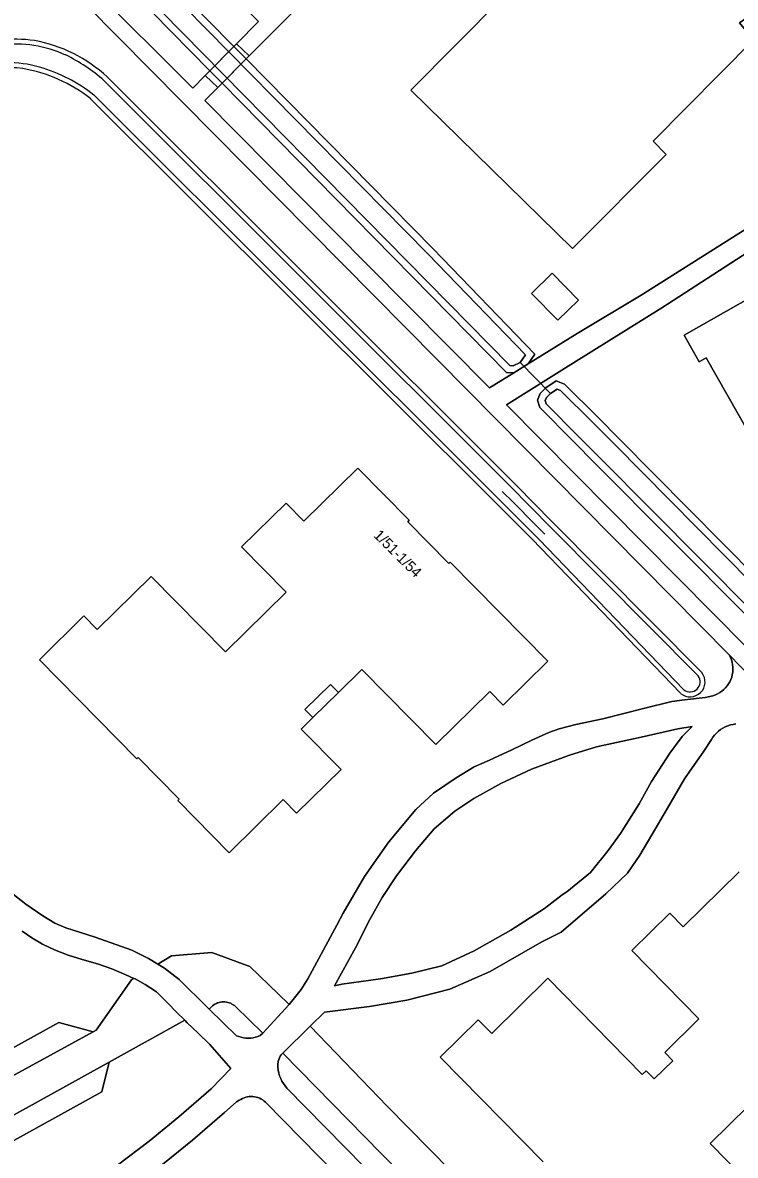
# Model space of a CAD drawing. Extents: x 162788 to 163838, y 385791 to 386523.
# Drawn here: x 162931.3 to 162998.4, y 386105.3 to 386211.9 of the extents above; entities that cross this region are included whole.
import ezdxf

# ---------------------------------------------------------------- set-up
doc = ezdxf.new("R2010")
doc.units = 0
for name, color, linetype in [('IMGEO_Berm_groen', 7, 'Continuous'), ('IMGEO_Dek', 7, 'Continuous'), ('IMGEO_Duiker', 7, 'Continuous'), ('IMGEO_Erf', 7, 'Continuous'), ('IMGEO_Groenvoorziening', 7, 'Continuous'), ('IMGEO_Oever', 7, 'Continuous'), ('IMGEO_Pand', 7, 'Continuous'), ('IMGEO_Pand_nummerreeks', 7, 'Continuous'), ('IMGEO_Pand_overbouw', 7, 'Continuous'), ('IMGEO_Parkeervlak_open', 7, 'Continuous'), ('IMGEO_Voetpad_open', 7, 'Continuous'), ('IMGEO_Waterloop', 7, 'Continuous'), ('IMGEO_Woonerf_gesloten', 7, 'Continuous'), ('IMGEO_Woonerf_open', 7, 'Continuous')]:
    doc.layers.add(name, color=color, linetype=linetype)

msp = doc.modelspace()

# ---------------------------------------------------------------- linework, layer by layer
at = {"layer": 'IMGEO_Berm_groen'}
msp.add_lwpolyline([(162965.08, 386105.45), (162955.83, 386114.88), (162955.67, 386114.72), (162955.58, 386114.62), (162955.43, 386114.28), (162955.37, 386114.1), (162955.36, 386113.83), (162955.36, 386113.56), (162955.39, 386113.29), (162955.45, 386113.02), (162955.52, 386112.76), (162955.62, 386112.51), (162955.74, 386112.26), (162955.87, 386112.02), (162956.03, 386111.8), (162956.21, 386111.59), (162968.96, 386098.61), (162970.91, 386096.63), (162971.01, 386099.41)], close=True, dxfattribs=at)
at = {"layer": 'IMGEO_Dek'}
msp.add_lwpolyline([(162952.65, 386208.77), (162951.46, 386209.9), (162948.52, 386206.92), (162949.69, 386205.79)], close=True, dxfattribs=at)
at = {"layer": 'IMGEO_Duiker'}
for points in [[(162981.02, 386176.99), (162978.18, 386179.89)], [(162980.5, 386163.74), (162979.58, 386164.66), (162977.5, 386166.74), (162976.48, 386167.77)]]:
    msp.add_lwpolyline(points, dxfattribs=at)
at = {"layer": 'IMGEO_Erf'}
for points in [[(162975.18, 386223.84), (162974.7, 386223.35), (162973.45, 386222.08), (162966.27, 386214.77), (162962.88, 386218.16), (162961.69, 386216.94), (162961.22, 386217.38), (162952.65, 386208.77), (162952.36, 386208.48), (162969.98, 386190.59), (162979.54, 386180.69), (162978.92, 386179.77), (162983.54, 386182.64), (162989.55, 386186.25), (163000.56, 386193.16), (163003.46, 386197.1), (163012.04, 386206.87), (163017.41, 386210.52), (163018.58, 386211.64), (163019.24, 386212.57)], [(163019.42, 386221.83), (163017.21, 386224.9), (163006.51, 386217.25), (163004.81, 386216.06), (162998.84, 386211.87), (163000, 386210.45), (163000.14, 386210.28), (162990.68, 386200.74), (162991.91, 386199.49), (162983.1, 386190.62), (162967.86, 386205.52), (162976.44, 386214.19), (162973.67, 386216.9), (162977.86, 386221.23), (162975.18, 386223.84)], [(162929.85, 386130.29), (162931.63, 386128.9), (162933.21, 386127.82), (162934.34, 386127.14), (162935.39, 386126.67), (162938.14, 386125.82), (162941.59, 386124.58), (162943.17, 386123.81), (162944.05, 386123.27), (162945.35, 386124.05), (162949.12, 386124.35), (162952.7, 386123.04), (162956.32, 386119.57), (162956.41, 386119.48), (162956.54, 386119.62), (162957.55, 386120.87), (162958.17, 386121.89), (162960.89, 386126.93), (162961.51, 386128.07), (162963.51, 386131.51), (162965.8, 386134.77), (162968.35, 386137.83), (162970.01, 386139.37), (162972.14, 386140.8), (162973.85, 386141.84), (162975.27, 386142.48), (162977.38, 386143.43), (162979.28, 386144.36), (162980.86, 386145.08), (162981.83, 386145.41), (162982.69, 386145.64), (162983.42, 386145.82), (162985.94, 386146.37), (162989.92, 386147.35), (162992.46, 386147.98), (162993.65, 386148.16), (162995.58, 386148.38), (162996.32, 386148.53), (162996.55, 386148.61), (162996.76, 386148.71), (162996.97, 386148.83), (162997.16, 386148.96), (162997.34, 386149.11), (162997.51, 386149.28), (162997.66, 386149.46), (162997.8, 386149.65), (162997.92, 386149.85), (162998.01, 386150.07), (162998.09, 386150.29), (162998.15, 386150.52), (162998.19, 386150.75), (162998.21, 386150.98), (162998.21, 386151.22), (162998.18, 386151.45), (162998.14, 386151.68), (162998.07, 386151.91), (162997.99, 386152.13), (162997.88, 386152.34), (162970.37, 386180.14), (162937.33, 386213.52)], [(162939.28, 386206.78), (162977.87, 386168.3), (162981.13, 386164.95), (162995.27, 386150.72)], [(162975.88, 386166.68), (162937.72, 386204.73)], [(163001.75, 386191.66), (162991.5, 386185.05), (162983.2, 386179.88), (162976.87, 386175.9), (163002.73, 386149.83)], [(163000.73, 386171.45), (162995.7, 386180.34), (162995.02, 386179.96), (162993.61, 386182.46), (163004.02, 386188.36)], [(162993.27, 386148.76), (162979.3, 386163.28), (162975.88, 386166.68)], [(162998.48, 386145.88), (162998.22, 386145.84), (162997.97, 386145.78), (162997.73, 386145.7), (162997.49, 386145.6), (162997.26, 386145.48), (162997.05, 386145.35), (162996.84, 386145.19), (162996.65, 386145.02), (162996.48, 386144.83), (162996.32, 386144.62), (162996.18, 386144.41), (162995.48, 386143.32), (162993.64, 386140.72), (162992.04, 386137.94), (162990.56, 386135.44), (162989.44, 386133.51), (162988.28, 386131.82), (162986.24, 386129.88), (162982.04, 386126.27), (162980.22, 386125.36), (162975.36, 386122.56), (162971.55, 386120.92), (162967.5, 386119.88), (162963.98, 386119.29), (162959.73, 386118.75), (162958.39, 386117.42), (162965.64, 386109.89), (162991.63, 386083.51)], [(162980.33, 386104.65), (162970.65, 386114.51), (162974.23, 386118.03), (162975.49, 386116.75), (162980.76, 386121.94), (162989.67, 386112.87), (162990.05, 386113.24), (162990.8, 386112.47), (162992.54, 386114.18), (162991.78, 386114.95), (162995.01, 386118.12), (162988.69, 386124.54), (162992.27, 386128.06), (162993.53, 386126.78), (162998.8, 386131.97)], [(163001.39, 386111.62), (162996.06, 386106.38), (163002.63, 386099.69)], [(162982.66, 386081.28), (162954.19, 386110.27), (162954.07, 386110.38), (162953.93, 386110.48), (162953.79, 386110.57), (162953.64, 386110.64), (162953.48, 386110.7), (162953.32, 386110.75), (162953.16, 386110.79), (162952.99, 386110.81), (162952.82, 386110.81), (162952.65, 386110.8), (162952.49, 386110.78), (162952.33, 386110.74), (162952.17, 386110.69), (162952.01, 386110.62), (162951.86, 386110.54), (162951.72, 386110.45), (162951.46, 386110.31), (162951.14, 386110.02), (162950.34, 386109.31), (162947.31, 386106.7), (162941.55, 386102.01)]]:
    msp.add_lwpolyline(points, dxfattribs=at)
for points in [[(162950.1, 386206.2), (162949.69, 386205.79), (162948.46, 386204.55), (162963.81, 386189.06), (162975.28, 386177.5), (162977.56, 386178.92), (162976.89, 386178.95)], [(162983.66, 386185.77), (162981.72, 386183.87), (162979.23, 386186.41), (162981.17, 386188.31)], [(163009.65, 386150.32), (163005.79, 386149.75), (162999.52, 386156.06), (162985.27, 386170.37), (162983.18, 386172.46), (162980.01, 386175.65), (162979.8, 386176.34), (162980.05, 386176.98), (162980.59, 386177.52), (162981.56, 386178.16), (162982.35, 386177.85), (162985.47, 386174.75), (162987.56, 386172.66), (163000.49, 386159.61)], [(162943.43, 386159.77), (162950.43, 386152.66), (162956.13, 386158.27), (162951.93, 386162.54), (162956.12, 386166.66), (162957.79, 386164.95), (162962.89, 386169.96), (162967.72, 386165.05), (162967.58, 386164.91), (162971.44, 386160.98), (162971.58, 386161.12), (162980.76, 386151.78), (162976.58, 386147.66), (162975.32, 386148.94), (162970.22, 386143.93), (162963.27, 386151.01), (162961.05, 386148.83), (162960.3, 386149.59), (162957.9, 386147.23), (162958.64, 386146.47), (162957.56, 386145.4), (162961.31, 386141.59), (162957.12, 386137.47), (162955.86, 386138.75), (162950.77, 386133.74), (162945.93, 386138.66), (162946.07, 386138.79), (162942.21, 386142.72), (162942.07, 386142.58), (162932.89, 386151.92), (162937.08, 386156.04), (162938.33, 386154.76)]]:
    msp.add_lwpolyline(points, close=True, dxfattribs=at)
for centre, radius, start, end in [((162930.67, 386198.51), 11.82, 81.3761, 97.3321), ((162929.86, 386196.5), 13.95, 47.5165, 79.3534), ((162930.2, 386198.17), 9.47, 83.2241, 110.3208), ((162928.95, 386193.6), 14.17, 51.7426, 80.3789), ((162994.17, 386149.84), 1.41, 230.3379, 38.4754)]:
    msp.add_arc(centre, radius, start, end, dxfattribs=at)
at = {"layer": 'IMGEO_Groenvoorziening'}
for points in [[(162938.72, 386222.33), (162951.21, 386209.65), (162952.36, 386208.48), (162952.65, 386208.77), (162951.46, 386209.9), (162953.54, 386212), (162949.2, 386216.43), (162952.32, 386219.35), (162953.06, 386218.56), (162955.11, 386216.45), (162952.97, 386214.36), (162954.44, 386212.91), (162960, 386218.54), (162957.98, 386220.46), (162959.31, 386221.73), (162955.49, 386225.56), (162979.88, 386249.93), (162983.46, 386246.58), (162984.89, 386248.89), (162987.74, 386256.11), (162989.77, 386258.92), (162997.17, 386269.16)], [(162935.59, 386221.29), (162932.71, 386218.4), (162933.58, 386217.52), (162936.66, 386214.37), (162937.76, 386215.29), (162947.33, 386205.72), (162948.52, 386206.92), (162949.69, 386205.79), (162950.1, 386206.2), (162948.95, 386207.36), (162936.25, 386220.28)], [(162925.05, 386112.43), (162934.71, 386117.77), (162937.97, 386116.9), (162938.25, 386117.05), (162941.57, 386121.79), (162941.79, 386121.92), (162941.04, 386122.26), (162939.71, 386122.83), (162938.35, 386123.31), (162936.91, 386123.71), (162935.61, 386124.12), (162934.32, 386124.62), (162933.2, 386125.16), (162932.19, 386125.73), (162931.26, 386126.36)], [(162929.79, 386099.11), (162932.96, 386100.21), (162935.59, 386101.26), (162937.76, 386102.46), (162940.24, 386104.34), (162943.24, 386106.61), (162946.03, 386108.9), (162949.06, 386111.52), (162950.92, 386113.46), (162948.95, 386115.69), (162947.8, 386116.79), (162946.82, 386117.74), (162946.59, 386117.98), (162939.45, 386114.03), (162938.78, 386111.25), (162928.69, 386105.68)]]:
    msp.add_lwpolyline(points, dxfattribs=at)
for points in [[(162960.69, 386121.24), (162961.37, 386121.37), (162965.02, 386121.89), (162967.98, 386122.41), (162970.78, 386123.12), (162973.83, 386124.53), (162977.29, 386126.48), (162980.46, 386128.51), (162982.12, 386129.8), (162982.56, 386130.07), (162984.8, 386131.9), (162986.46, 386133.98), (162987.62, 386135.57), (162989.37, 386138.37), (162990.55, 386140.45), (162992.26, 386143.12), (162993.42, 386144.71), (162994.37, 386145.65), (162993.02, 386145.41), (162989.57, 386144.62), (162985.35, 386143.71), (162982.82, 386142.95), (162979.24, 386141.61), (162976.35, 386140.28), (162973.82, 386138.87), (162972.02, 386137.68), (162970.07, 386135.99), (162968.32, 386133.93), (162966.53, 386131.58), (162965.16, 386129.54), (162964.01, 386127.47), (162962.65, 386124.79)], [(162948.89, 386119.03), (162951.46, 386116.53), (162951.68, 386116.45), (162951.89, 386116.38), (162952.12, 386116.33), (162952.35, 386116.3), (162952.58, 386116.3), (162952.8, 386116.31), (162953.03, 386116.34), (162953.25, 386116.4), (162953.47, 386116.47), (162953.68, 386116.56), (162953.93, 386116.76), (162951.37, 386119.27), (162951.26, 386119.36), (162951.15, 386119.44), (162951.03, 386119.51), (162950.91, 386119.58), (162950.78, 386119.63), (162950.64, 386119.67), (162950.51, 386119.7), (162950.37, 386119.71), (162950.23, 386119.72), (162950.09, 386119.71), (162949.95, 386119.69), (162949.82, 386119.66), (162949.68, 386119.62), (162949.56, 386119.56), (162949.43, 386119.5), (162949.31, 386119.43), (162949.2, 386119.34), (162949.1, 386119.25)]]:
    msp.add_lwpolyline(points, close=True, dxfattribs=at)
at = {"layer": 'IMGEO_Oever'}
for points in [[(162938.23, 386221.85), (162969.49, 386190.12)], [(162952.36, 386208.48), (162951.21, 386209.65), (162938.72, 386222.33)], [(162969.49, 386190.12), (162978.67, 386180.61), (162978.18, 386179.89), (162977.51, 386179.6), (162977.19, 386179.62), (162936.74, 386220.75)], [(162936.25, 386220.28), (162948.95, 386207.36), (162950.1, 386206.2), (162976.89, 386178.95), (162977.56, 386178.92), (162978.92, 386179.77), (162979.54, 386180.69), (162969.98, 386190.59), (162952.36, 386208.48)], [(162995.27, 386150.72), (162981.13, 386164.95), (162977.87, 386168.3), (162939.28, 386206.78)], [(162938.97, 386206.44), (162977.18, 386168.33), (162981.12, 386164.31), (162994.92, 386150.41)], [(162937.72, 386204.73), (162975.88, 386166.68), (162979.3, 386163.28), (162993.27, 386148.76)], [(162993.59, 386149.1), (162979.97, 386163.25), (162975.91, 386167.3), (162938.03, 386205.08)]]:
    msp.add_lwpolyline(points, dxfattribs=at)
for points in [[(162982.35, 386177.85), (162981.56, 386178.16), (162980.59, 386177.52), (162980.05, 386176.98), (162979.8, 386176.34), (162980.01, 386175.65), (162983.18, 386172.46), (162985.27, 386170.37), (162999.52, 386156.06), (163005.79, 386149.75), (163009.65, 386150.32), (163000.49, 386159.61), (162987.56, 386172.66), (162985.47, 386174.75)], [(162984.99, 386174.27), (162987.08, 386172.18), (163000, 386159.13), (163008.22, 386150.8), (163006.03, 386150.48), (163000, 386156.54), (162985.75, 386170.85), (162983.67, 386172.94), (162980.61, 386176.01), (162980.52, 386176.31), (162980.64, 386176.6), (162981.02, 386176.99), (162981.64, 386177.4), (162981.97, 386177.27)]]:
    msp.add_lwpolyline(points, close=True, dxfattribs=at)
for centre, radius, start, end in [((162930.67, 386198.51), 11.82, 81.3761, 97.3321), ((162929.86, 386196.5), 13.95, 47.5165, 79.3534), ((162930.67, 386198.55), 11.32, 65.3939, 97.2288), ((162930.13, 386198.75), 9.36, 72.7501, 111.3612), ((162927.99, 386193.95), 16.63, 48.6994, 63.6037), ((162930.2, 386198.17), 9.47, 83.2241, 110.3208), ((162928.95, 386193.6), 14.17, 51.7426, 80.3789), ((162928.85, 386193.44), 14.82, 51.747, 74.1345), ((162994.17, 386149.84), 1.41, 230.3379, 38.4754), ((162994.17, 386149.84), 0.944, 231.7804, 37.0508)]:
    msp.add_arc(centre, radius, start, end, dxfattribs=at)
at = {"layer": 'IMGEO_Pand'}
for points in [[(163004.71, 386220.78), (163012.99, 386226.74), (163001.49, 386242.78), (162990.89, 386235.2), (162988.57, 386237.48), (162975.18, 386223.84), (162977.86, 386221.23), (162973.67, 386216.9), (162976.44, 386214.19), (162967.86, 386205.52), (162983.1, 386190.62), (162991.91, 386199.49), (162990.68, 386200.74), (163000.14, 386210.28), (163000, 386210.45), (162998.84, 386211.87), (163004.81, 386216.06), (163002.53, 386219.21), (163004.16, 386220.38)], [(162983.66, 386185.77), (162981.17, 386188.31), (162979.23, 386186.41), (162981.72, 386183.87)], [(162957.9, 386147.23), (162960.3, 386149.59), (162961.05, 386148.83), (162963.27, 386151.01), (162970.22, 386143.93), (162975.32, 386148.94), (162976.58, 386147.66), (162980.76, 386151.78), (162971.58, 386161.12), (162971.44, 386160.98), (162967.58, 386164.91), (162967.72, 386165.05), (162962.89, 386169.96), (162957.79, 386164.95), (162956.12, 386166.66), (162951.93, 386162.54), (162956.13, 386158.27), (162950.43, 386152.66), (162943.43, 386159.77), (162938.33, 386154.76), (162937.08, 386156.04), (162932.89, 386151.92), (162942.07, 386142.58), (162942.21, 386142.72), (162946.07, 386138.79), (162945.93, 386138.66), (162950.77, 386133.74), (162955.86, 386138.75), (162957.12, 386137.47), (162961.31, 386141.59), (162957.56, 386145.4), (162958.64, 386146.47)]]:
    msp.add_lwpolyline(points, close=True, dxfattribs=at)
for points in [[(163004.02, 386188.36), (162993.61, 386182.46), (162995.02, 386179.96), (162995.7, 386180.34), (163000.73, 386171.45)], [(162998.8, 386131.97), (162993.53, 386126.78), (162992.27, 386128.06), (162988.69, 386124.54), (162995.01, 386118.12), (162991.78, 386114.95), (162992.54, 386114.18), (162990.8, 386112.47), (162990.05, 386113.24), (162989.67, 386112.87), (162980.76, 386121.94), (162975.49, 386116.75), (162974.23, 386118.03), (162970.65, 386114.51), (162980.33, 386104.65)], [(163002.63, 386099.69), (162996.06, 386106.38), (163001.39, 386111.62)]]:
    msp.add_lwpolyline(points, dxfattribs=at)
at = {"layer": 'IMGEO_Pand_overbouw'}
msp.add_lwpolyline([(162961.05, 386148.83), (162960.3, 386149.59), (162957.9, 386147.23), (162958.64, 386146.47)], close=True, dxfattribs=at)
at = {"layer": 'IMGEO_Parkeervlak_open'}
for points in [[(162937.97, 386116.9), (162934.71, 386117.77), (162925.05, 386112.43), (162924.21, 386109.41)], [(162939.45, 386114.03), (162925.79, 386106.48), (162928.69, 386105.68), (162938.78, 386111.25)]]:
    msp.add_lwpolyline(points, close=True, dxfattribs=at)
at = {"layer": 'IMGEO_Voetpad_open'}
for points in [[(162961.22, 386217.38), (162960, 386218.54), (162954.44, 386212.91), (162952.97, 386214.36), (162950.92, 386216.46), (162953.06, 386218.56), (162952.32, 386219.35), (162949.2, 386216.43), (162953.54, 386212), (162951.46, 386209.9), (162952.65, 386208.77)], [(162952.65, 386208.77), (162951.46, 386209.9), (162951.21, 386209.65), (162948.95, 386207.36), (162948.52, 386206.92), (162949.69, 386205.79), (162952.36, 386208.48)]]:
    msp.add_lwpolyline(points, close=True, dxfattribs=at)
at = {"layer": 'IMGEO_Waterloop'}
for points in [[(162936.74, 386220.75), (162977.19, 386179.62), (162977.51, 386179.6), (162978.18, 386179.89), (162978.67, 386180.61), (162969.49, 386190.12), (162938.23, 386221.85)], [(162994.92, 386150.41), (162981.12, 386164.31), (162977.18, 386168.33), (162938.97, 386206.44)], [(162938.03, 386205.08), (162975.91, 386167.3), (162979.97, 386163.25), (162993.59, 386149.1)]]:
    msp.add_lwpolyline(points, dxfattribs=at)
msp.add_lwpolyline([(162981.97, 386177.27), (162981.64, 386177.4), (162981.02, 386176.99), (162980.64, 386176.6), (162980.52, 386176.31), (162980.61, 386176.01), (162983.67, 386172.94), (162985.75, 386170.85), (163000, 386156.54), (163006.03, 386150.48), (163008.22, 386150.8), (163000, 386159.13), (162987.08, 386172.18), (162984.99, 386174.27)], close=True, dxfattribs=at)
for centre, radius, start, end in [((162930.67, 386198.55), 11.32, 65.3939, 97.2288), ((162930.13, 386198.75), 9.36, 72.7501, 111.3612), ((162927.99, 386193.95), 16.63, 48.6994, 63.6037), ((162928.85, 386193.44), 14.82, 51.747, 74.1345), ((162994.17, 386149.84), 0.944, 231.7804, 37.0508)]:
    msp.add_arc(centre, radius, start, end, dxfattribs=at)
at = {"layer": 'IMGEO_Woonerf_gesloten'}
for points in [[(163004.76, 386145.27), (162997.88, 386152.34), (162997.99, 386152.13), (162998.07, 386151.91), (162998.14, 386151.68), (162998.18, 386151.45), (162998.21, 386151.22), (162998.21, 386150.98), (162998.19, 386150.75), (162998.15, 386150.52), (162998.09, 386150.29), (162998.01, 386150.07), (162997.92, 386149.85), (162997.8, 386149.65), (162997.66, 386149.46), (162997.51, 386149.28), (162997.34, 386149.11), (162997.16, 386148.96), (162996.97, 386148.83), (162996.76, 386148.71), (162996.55, 386148.61), (162996.32, 386148.53), (162995.58, 386148.38), (162993.65, 386148.16), (162992.46, 386147.98), (162989.92, 386147.35), (162985.94, 386146.37), (162983.42, 386145.82), (162982.69, 386145.64), (162981.83, 386145.41), (162980.86, 386145.08), (162979.28, 386144.36), (162977.38, 386143.43), (162975.27, 386142.48), (162973.85, 386141.84), (162972.14, 386140.8), (162970.01, 386139.37), (162968.35, 386137.83), (162965.8, 386134.77), (162963.51, 386131.51), (162961.51, 386128.07), (162960.89, 386126.93), (162958.17, 386121.89), (162957.55, 386120.87), (162956.54, 386119.62), (162956.41, 386119.48), (162953.93, 386116.76), (162953.68, 386116.56), (162953.47, 386116.47), (162953.25, 386116.4), (162953.03, 386116.34), (162952.8, 386116.31), (162952.58, 386116.3), (162952.35, 386116.3), (162952.12, 386116.33), (162951.89, 386116.38), (162951.68, 386116.45), (162951.46, 386116.53), (162948.89, 386119.03), (162948.72, 386119.2), (162946.05, 386121.83), (162944.66, 386122.89), (162944.05, 386123.27), (162943.17, 386123.81), (162941.59, 386124.58), (162938.14, 386125.82), (162935.39, 386126.67), (162934.34, 386127.14), (162933.21, 386127.82), (162931.63, 386128.9), (162929.85, 386130.29)], [(162968.96, 386098.61), (162956.21, 386111.59), (162956.03, 386111.8), (162955.87, 386112.02), (162955.74, 386112.26), (162955.62, 386112.51), (162955.52, 386112.76), (162955.45, 386113.02), (162955.39, 386113.29), (162955.36, 386113.56), (162955.36, 386113.83), (162955.37, 386114.1), (162955.43, 386114.28), (162955.58, 386114.62), (162955.67, 386114.72), (162955.83, 386114.88), (162958.39, 386117.42), (162959.73, 386118.75), (162963.98, 386119.29), (162967.5, 386119.88), (162971.55, 386120.92), (162975.36, 386122.56), (162980.22, 386125.36), (162982.04, 386126.27), (162986.24, 386129.88), (162988.28, 386131.82), (162989.44, 386133.51), (162990.56, 386135.44), (162992.04, 386137.94), (162993.64, 386140.72), (162995.48, 386143.32), (162996.18, 386144.41), (162996.32, 386144.62), (162996.48, 386144.83), (162996.65, 386145.02), (162996.84, 386145.19), (162997.05, 386145.35), (162997.26, 386145.48), (162997.49, 386145.6), (162997.73, 386145.7), (162997.97, 386145.78), (162998.22, 386145.84), (162998.48, 386145.88)], [(162931.26, 386126.36), (162932.19, 386125.73), (162933.2, 386125.16), (162934.32, 386124.62), (162935.61, 386124.12), (162936.91, 386123.71), (162938.35, 386123.31), (162939.71, 386122.83), (162941.04, 386122.26), (162941.79, 386121.92), (162941.91, 386121.87), (162942.84, 386121.35), (162943.91, 386120.65), (162944.96, 386119.64), (162945.83, 386118.73), (162946.59, 386117.98), (162946.82, 386117.74), (162947.8, 386116.79), (162948.95, 386115.69), (162950.92, 386113.46), (162949.06, 386111.52), (162946.03, 386108.9), (162943.24, 386106.61), (162940.24, 386104.34)], [(162941.55, 386102.01), (162947.31, 386106.7), (162950.34, 386109.31), (162951.14, 386110.02), (162951.46, 386110.31), (162951.72, 386110.45), (162951.86, 386110.54), (162952.01, 386110.62), (162952.17, 386110.69), (162952.33, 386110.74), (162952.49, 386110.78), (162952.65, 386110.8), (162952.82, 386110.81), (162952.99, 386110.81), (162953.16, 386110.79), (162953.32, 386110.75), (162953.48, 386110.7), (162953.64, 386110.64), (162953.79, 386110.57), (162953.93, 386110.48), (162954.07, 386110.38), (162954.19, 386110.27), (162982.66, 386081.28)]]:
    msp.add_lwpolyline(points, dxfattribs=at)
msp.add_lwpolyline([(162977.29, 386126.48), (162973.83, 386124.53), (162970.78, 386123.12), (162967.98, 386122.41), (162965.02, 386121.89), (162961.37, 386121.37), (162960.69, 386121.24), (162962.65, 386124.79), (162964.01, 386127.47), (162965.16, 386129.54), (162966.53, 386131.58), (162968.32, 386133.93), (162970.07, 386135.99), (162972.02, 386137.68), (162973.82, 386138.87), (162976.35, 386140.28), (162979.24, 386141.61), (162982.82, 386142.95), (162985.35, 386143.71), (162989.57, 386144.62), (162993.02, 386145.41), (162994.37, 386145.65), (162993.42, 386144.71), (162992.26, 386143.12), (162990.55, 386140.45), (162989.37, 386138.37), (162987.62, 386135.57), (162986.46, 386133.98), (162984.8, 386131.9), (162982.56, 386130.07), (162982.12, 386129.8), (162980.46, 386128.51)], close=True, dxfattribs=at)
at = {"layer": 'IMGEO_Woonerf_open'}
for points in [[(163000.56, 386193.16), (162989.55, 386186.25), (162983.54, 386182.64), (162978.92, 386179.77), (162977.56, 386178.92), (162975.28, 386177.5), (162963.81, 386189.06), (162948.46, 386204.55), (162949.69, 386205.79), (162948.52, 386206.92), (162947.33, 386205.72), (162937.76, 386215.29)], [(162937.33, 386213.52), (162970.37, 386180.14), (162997.88, 386152.34), (163004.76, 386145.27), (163006.09, 386144.1), (163009.12, 386141.02), (163031.42, 386118.47), (163036.33, 386113.74), (163041.32, 386108.18), (163041.52, 386108.01), (163041.71, 386107.83), (163049.21, 386100.56)], [(163002.73, 386149.83), (162976.87, 386175.9), (162983.2, 386179.88), (162991.5, 386185.05), (163001.75, 386191.66)], [(162925.79, 386106.48), (162939.45, 386114.03), (162946.59, 386117.98), (162945.83, 386118.73), (162944.96, 386119.64), (162943.91, 386120.65), (162942.84, 386121.35), (162941.91, 386121.87), (162941.79, 386121.92), (162941.57, 386121.79), (162938.25, 386117.05), (162937.97, 386116.9), (162924.21, 386109.41)]]:
    msp.add_lwpolyline(points, dxfattribs=at)
for points in [[(162952.7, 386123.04), (162949.12, 386124.35), (162945.35, 386124.05), (162944.05, 386123.27), (162944.66, 386122.89), (162946.05, 386121.83), (162948.72, 386119.2), (162948.89, 386119.03), (162949.1, 386119.25), (162949.2, 386119.34), (162949.31, 386119.43), (162949.43, 386119.5), (162949.56, 386119.56), (162949.68, 386119.62), (162949.82, 386119.66), (162949.95, 386119.69), (162950.09, 386119.71), (162950.23, 386119.72), (162950.37, 386119.71), (162950.51, 386119.7), (162950.64, 386119.67), (162950.78, 386119.63), (162950.91, 386119.58), (162951.03, 386119.51), (162951.15, 386119.44), (162951.26, 386119.36), (162951.37, 386119.27), (162953.93, 386116.76), (162956.41, 386119.48), (162956.32, 386119.57)], [(162965.64, 386109.89), (162958.39, 386117.42), (162955.83, 386114.88), (162965.08, 386105.45), (162971.01, 386099.41), (162983.38, 386086.82), (162989.08, 386081.02), (162991.63, 386083.51)]]:
    msp.add_lwpolyline(points, close=True, dxfattribs=at)

# ---------------------------------------------------------------- texts
at = {"layer": 'IMGEO_Pand_nummerreeks'}
msp.add_text('1/51-1/54', height=1, rotation=315.151, dxfattribs=at).set_placement((162964.29, 386163.56))

doc.saveas('drawing.dxf')
